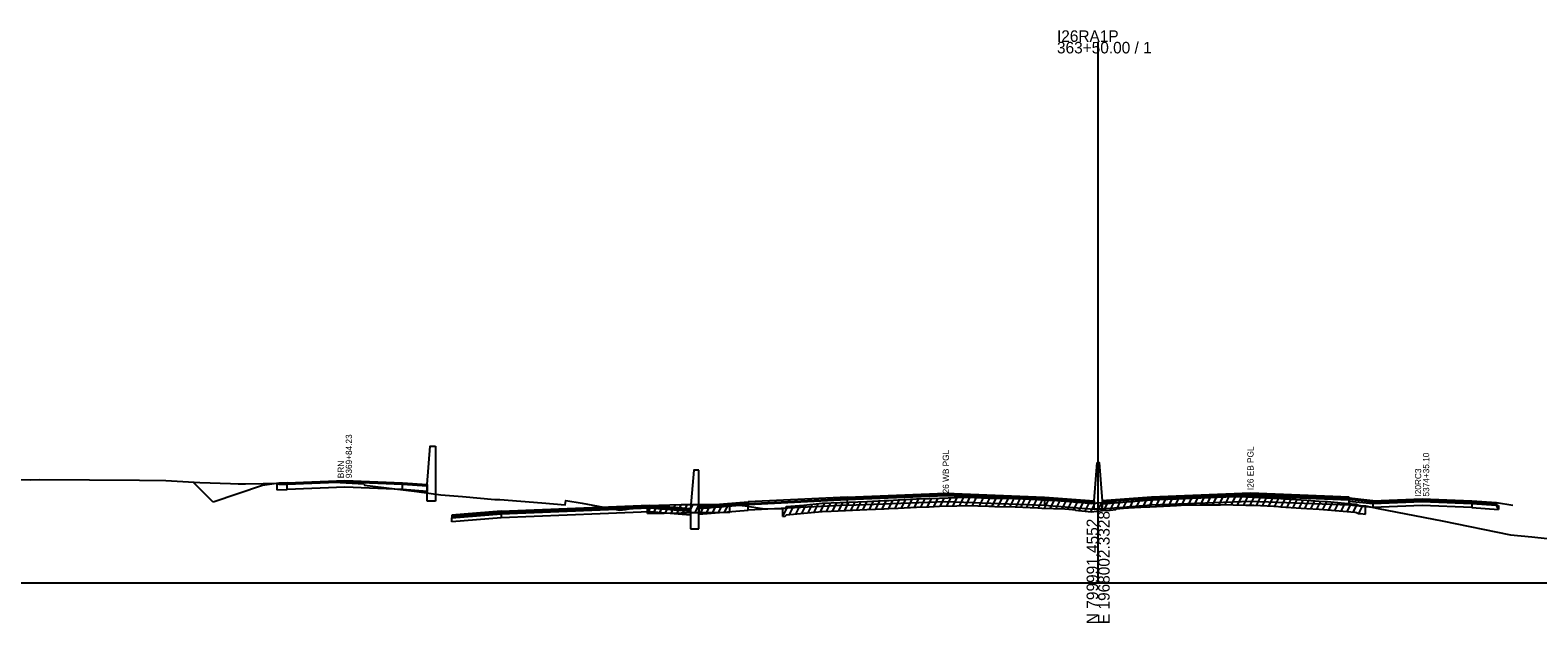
# Model space of a CAD drawing. Extents: x 1017 to 19997, y -1947 to 50737.
# Drawn here: x 14340.6 to 14706.8, y 13490.3 to 13634.3 of the extents above; entities that cross this region are included whole.
import ezdxf

# ---------------------------------------------------------------- set-up
doc = ezdxf.new("R2010")
doc.units = 0
for name, color, linetype in [('RD_GPK_XS_Cell', 7, 'Continuous'), ('RD_XS_Base', 7, 'Continuous'), ('RD_XS_ExGround', 7, 'Continuous'), ('RD_XS_ExPaveRet', 7, 'Continuous'), ('RD_XS_Greenside', 7, 'Continuous'), ('RD_XS_MedBWall', 7, 'Continuous'), ('RD_XS_Pave', 7, 'Continuous'), ('RD_XS_PaveOvlay', 7, 'Continuous'), ('RD_XS_TieSlope', 7, 'Continuous'), ('RD_XS_TX_Notes', 7, 'Continuous')]:
    doc.layers.add(name, color=color, linetype=linetype)

msp = doc.modelspace()

# ---------------------------------------------------------------- linework, layer by layer
at = {"layer": 'RD_GPK_XS_Cell'}
for p, q in [((14600, 13500), (14600, 13631.42)), ((14000, 13500), (14600, 13500)), ((14600, 13500), (15200, 13500))]:
    msp.add_line(p, q, dxfattribs=at)
at = {"layer": 'RD_XS_Base'}
for points in [[(14403, 13524.03), (14400.5, 13523.93)], [(14400.5, 13523.93), (14400.5, 13522.6)], [(14400.5, 13522.6), (14403, 13522.7)], [(14403, 13524.03), (14417, 13524.59), (14431, 13524.03)], [(14403, 13522.7), (14403, 13524.03)], [(14431, 13522.72), (14417, 13523.26), (14403, 13522.7)], [(14431, 13522.72), (14431, 13524.03)], [(14431, 13524.03), (14437, 13523.55)], [(14437, 13522.24), (14431, 13522.72)], [(14437, 13523.55), (14437, 13522.24)], [(14515, 13517.64), (14515, 13518.98)], [(14539.05, 13518.85), (14515, 13517.64)], [(14539.05, 13520.19), (14539.05, 13518.85)], [(14539.05, 13518.85), (14563, 13519.82), (14587, 13518.85)], [(14599, 13519.25), (14587, 13520.19)], [(14587, 13520.19), (14587, 13518.85)], [(14587, 13518.85), (14599, 13517.91)], [(14599, 13517.91), (14599, 13519.25)], [(14601, 13517.91), (14601, 13519.25)], [(14613, 13518.85), (14601, 13517.91)], [(14613, 13518.85), (14613, 13520.19)], [(14660.95, 13518.85), (14637, 13519.82), (14613, 13518.85)], [(14660.95, 13518.85), (14660.95, 13520.19)], [(14660.95, 13518.9), (14660.95, 13519.9)], [(14660.95, 13519.9), (14666.73, 13519.29)], [(14666.73, 13518.29), (14660.95, 13518.9)], [(14661, 13518.85), (14660.95, 13518.85)], [(14661, 13520.19), (14661, 13518.85)], [(14666.73, 13519.29), (14666.73, 13518.29)], [(14690.76, 13518.33), (14678.74, 13518.79), (14666.73, 13518.29)], [(14690.76, 13519.33), (14690.76, 13518.33)], [(14697.26, 13517.83), (14696.76, 13518.87), (14690.76, 13519.33)], [(14690.76, 13519.33), (14696.76, 13518.87), (14697.26, 13518.83)], [(14697.26, 13518.83), (14697.26, 13517.83)], [(14443, 13515.83), (14455, 13516.81)], [(14443, 13514.83), (14443, 13515.83)], [(14455, 13515.81), (14443, 13514.83)], [(14491, 13517.25), (14479, 13516.77), (14455, 13515.81)], [(14455, 13516.81), (14455, 13515.81)], [(14491, 13518.25), (14501, 13517.45)], [(14491, 13517.25), (14491, 13518.25)], [(14501, 13516.45), (14491, 13517.25)], [(14501, 13517.45), (14501, 13516.45)], [(14503, 13518.02), (14503, 13516.68)], [(14503, 13516.68), (14515, 13517.64)], [(14690.76, 13518.33), (14697.26, 13517.83)]]:
    msp.add_lwpolyline(points, dxfattribs=at)
at = {"layer": 'RD_XS_ExGround'}
msp.add_lwpolyline([(14337.99, 13525.12), (14340.57, 13525.08), (14342.85, 13525.12), (14367.13, 13524.96), (14373.55, 13524.89), (14381.74, 13524.38), (14389.24, 13524.14), (14391.1, 13524.11), (14392.91, 13524.06), (14397.2, 13524.15), (14403.93, 13524.24), (14411.6, 13524.52), (14414.45, 13524.46), (14421.67, 13524.11), (14421.77, 13523.71), (14433.82, 13522.31), (14434.49, 13522.22), (14440.35, 13521.42), (14445.62, 13521), (14453.46, 13520.28), (14454.65, 13520.29), (14464.82, 13519.45), (14470.56, 13519), (14470.66, 13520), (14474.65, 13519.39), (14478.57, 13518.68), (14482.11, 13517.96), (14483.73, 13517.7), (14485.22, 13517.87), (14490.53, 13518.84), (14498.71, 13519.04), (14500.63, 13519.09), (14504.46, 13519.09), (14510.53, 13519.16), (14514.23, 13518.71), (14518.92, 13518.03), (14523.38, 13518.1), (14523.94, 13518.2), (14524.31, 13518.53), (14528.48, 13518.92), (14532.99, 13519.36), (14535.14, 13519.42), (14543.78, 13519.8), (14548.03, 13519.99), (14549.15, 13520.06), (14551.43, 13520.18), (14555.89, 13520.4), (14558.99, 13520.52), (14561.5, 13520.61), (14565.65, 13520.74), (14568.12, 13520.83), (14573.43, 13520.63), (14574.11, 13520.61), (14574.93, 13520.59), (14579.84, 13520.52), (14585.39, 13520.25), (14586.34, 13520.2), (14591.88, 13519.97), (14593.79, 13519.84), (14594.34, 13519.8), (14594.54, 13519.65), (14595.25, 13519.6), (14598.37, 13519.29), (14599.6, 13519.43), (14600, 13519.47), (14601.09, 13519.57), (14602.89, 13519.69), (14604.26, 13519.8), (14604.47, 13519.97), (14606.16, 13520.14), (14607.35, 13520.25), (14610.35, 13520.38), (14612.54, 13520.49), (14617.5, 13520.75), (14619.03, 13520.83), (14620.16, 13520.85), (14624.68, 13520.97), (14629.75, 13521.01), (14630.84, 13521.02), (14632.83, 13520.98), (14635.9, 13520.92), (14636.81, 13520.88), (14637.84, 13520.86), (14642.69, 13520.63), (14643.13, 13520.61), (14644.41, 13520.51), (14649.36, 13520.16), (14650.68, 13520.07), (14653.71, 13519.9), (14655.74, 13519.76), (14662.34, 13519.17), (14662.78, 13519.13), (14663.21, 13518.88), (14663.71, 13518.83), (14664.92, 13518.7), (14668.04, 13518.12), (14683.57, 13515.08), (14700.21, 13511.66), (14705.36, 13511.17), (14709.1, 13510.8)], dxfattribs=at)
at = {"layer": 'RD_XS_ExPaveRet'}
for p, q in [((14490.53, 13516.84), (14491.55, 13518.87)), ((14490.53, 13516.84), (14490.53, 13518.84)), ((14491.98, 13516.88), (14492.99, 13518.9)), ((14493.42, 13516.91), (14494.43, 13518.94)), ((14494.86, 13516.95), (14495.88, 13518.97)), ((14496.31, 13516.98), (14497.32, 13519.01)), ((14497.75, 13517.02), (14498.76, 13519.05)), ((14499.2, 13517.06), (14500.21, 13519.08)), ((14500.66, 13517.09), (14501.66, 13519.09)), ((14502.08, 13517.09), (14503.08, 13519.09)), ((14503.51, 13517.09), (14504.51, 13519.09)), ((14504.94, 13517.09), (14505.94, 13519.11)), ((14506.37, 13517.11), (14507.37, 13519.12)), ((14507.81, 13517.13), (14508.82, 13519.14)), ((14509.26, 13517.15), (14510.27, 13519.16)), ((14510.53, 13517.16), (14510.53, 13519.16)), ((14523.38, 13516.1), (14524.61, 13518.56)), ((14525.06, 13516.6), (14526.11, 13518.7)), ((14526.56, 13516.74), (14527.61, 13518.84)), ((14528.05, 13516.88), (14529.1, 13518.98)), ((14529.55, 13517.03), (14530.6, 13519.13)), ((14531.04, 13517.17), (14532.09, 13519.27)), ((14532.55, 13517.32), (14533.58, 13519.38)), ((14534.03, 13517.39), (14535.04, 13519.42)), ((14535.49, 13517.44), (14536.51, 13519.48)), ((14536.97, 13517.5), (14537.99, 13519.55)), ((14538.44, 13517.57), (14539.46, 13519.61)), ((14539.91, 13517.63), (14540.94, 13519.68)), ((14541.39, 13517.7), (14542.41, 13519.74)), ((14542.87, 13517.76), (14543.89, 13519.81)), ((14544.42, 13517.83), (14545.44, 13519.88)), ((14545.98, 13517.9), (14547, 13519.94)), ((14547.54, 13517.97), (14548.57, 13520.02)), ((14549.12, 13518.06), (14550.15, 13520.11)), ((14550.69, 13518.14), (14551.71, 13520.19)), ((14552.26, 13518.22), (14553.28, 13520.27)), ((14553.82, 13518.29), (14554.85, 13520.35)), ((14555.39, 13518.37), (14556.41, 13520.42)), ((14556.96, 13518.44), (14557.98, 13520.48)), ((14558.53, 13518.51), (14559.55, 13520.54)), ((14560.09, 13518.56), (14561.11, 13520.59)), ((14561.65, 13518.61), (14562.67, 13520.64)), ((14563.21, 13518.66), (14564.23, 13520.69)), ((14564.77, 13518.71), (14565.79, 13520.74)), ((14566.33, 13518.76), (14567.35, 13520.8)), ((14567.89, 13518.82), (14568.88, 13520.8)), ((14569.47, 13518.78), (14570.45, 13520.74)), ((14571.21, 13518.71), (14572.19, 13520.67)), ((14572.72, 13518.65), (14573.7, 13520.62)), ((14574.24, 13518.6), (14575.23, 13520.59)), ((14575.72, 13518.58), (14576.71, 13520.57)), ((14577.19, 13518.56), (14578.19, 13520.54)), ((14578.63, 13518.54), (14579.63, 13520.52)), ((14580.06, 13518.51), (14581.04, 13520.46)), ((14581.29, 13518.45), (14582.27, 13520.4)), ((14582.67, 13518.38), (14583.65, 13520.33)), ((14584.1, 13518.31), (14585.07, 13520.26)), ((14585.52, 13518.24), (14586.5, 13520.2)), ((14586.95, 13518.18), (14587.93, 13520.14)), ((14588.38, 13518.12), (14589.36, 13520.08)), ((14589.81, 13518.06), (14590.79, 13520.02)), ((14591.24, 13518), (14592.21, 13519.95)), ((14592.65, 13517.92), (14593.62, 13519.85)), ((14594.06, 13517.82), (14594.96, 13519.62)), ((14595.43, 13517.58), (14596.38, 13519.49)), ((14596.84, 13517.44), (14597.79, 13519.34)), ((14598.25, 13517.3), (14599.3, 13519.4)), ((14599.81, 13517.45), (14600.86, 13519.55)), ((14601.37, 13517.59), (14602.4, 13519.65)), ((14602.9, 13517.69), (14603.94, 13519.77)), ((14604.53, 13517.98), (14605.58, 13520.08)), ((14606.09, 13518.14), (14607.14, 13520.23)), ((14607.69, 13518.26), (14608.71, 13520.31)), ((14609.26, 13518.33), (14610.29, 13520.37)), ((14610.84, 13518.4), (14611.87, 13520.46)), ((14612.42, 13518.49), (14613.45, 13520.54)), ((14614, 13518.57), (14615.03, 13520.62)), ((14615.58, 13518.65), (14616.61, 13520.7)), ((14617.16, 13518.73), (14618.18, 13520.78)), ((14618.74, 13518.81), (14619.75, 13520.84)), ((14620.31, 13518.86), (14621.32, 13520.88)), ((14621.89, 13518.9), (14622.9, 13520.92)), ((14623.39, 13518.94), (14624.4, 13520.96)), ((14624.89, 13518.97), (14625.9, 13520.98)), ((14626.38, 13518.99), (14627.39, 13520.99)), ((14627.87, 13519), (14628.87, 13521)), ((14629.36, 13519.01), (14630.37, 13521.02)), ((14630.85, 13519.02), (14631.84, 13521)), ((14632.37, 13518.99), (14633.36, 13520.97)), ((14633.89, 13518.96), (14634.89, 13520.94)), ((14635.42, 13518.93), (14636.4, 13520.9)), ((14636.93, 13518.88), (14637.92, 13520.85)), ((14638.45, 13518.83), (14639.42, 13520.78)), ((14639.95, 13518.76), (14640.93, 13520.71)), ((14641.45, 13518.68), (14642.43, 13520.64)), ((14642.96, 13518.61), (14643.92, 13520.55)), ((14644.45, 13518.51), (14645.42, 13520.44)), ((14645.95, 13518.4), (14646.92, 13520.33)), ((14647.39, 13518.3), (14648.35, 13520.23)), ((14648.82, 13518.2), (14649.79, 13520.13)), ((14650.25, 13518.1), (14651.22, 13520.04)), ((14651.7, 13518.01), (14652.67, 13519.96)), ((14653.14, 13517.93), (14654.11, 13519.88)), ((14654.58, 13517.84), (14655.55, 13519.78)), ((14656.06, 13517.73), (14657.02, 13519.65)), ((14657.53, 13517.6), (14658.49, 13519.52)), ((14659.01, 13517.47), (14659.97, 13519.39)), ((14660.48, 13517.34), (14661.44, 13519.25)), ((14661.95, 13517.21), (14662.89, 13519.07)), ((14663.33, 13516.87), (14664.28, 13518.77)), ((14664.92, 13516.7), (14664.92, 13518.7)), ((14523.38, 13516.1), (14523.38, 13518.1)), ((14664.79, 13516.72), (14664.92, 13516.99))]:
    msp.add_line(p, q, dxfattribs=at)
for points in [[(14523.38, 13516.1), (14523.94, 13516.2), (14524.31, 13516.53), (14528.48, 13516.92), (14532.99, 13517.36), (14535.14, 13517.42), (14543.78, 13517.8), (14548.03, 13517.99), (14549.15, 13518.06), (14551.43, 13518.18), (14555.89, 13518.4), (14558.99, 13518.52), (14561.5, 13518.61), (14565.65, 13518.74), (14568.12, 13518.83), (14573.43, 13518.63), (14574.11, 13518.61), (14574.93, 13518.59), (14579.84, 13518.52), (14585.39, 13518.25), (14586.34, 13518.2), (14591.88, 13517.97), (14593.79, 13517.84), (14594.34, 13517.8), (14594.54, 13517.65), (14595.25, 13517.6), (14598.37, 13517.29), (14599.6, 13517.43), (14600, 13517.47), (14601.09, 13517.57), (14602.89, 13517.69), (14604.26, 13517.8), (14604.47, 13517.97), (14606.16, 13518.14), (14607.35, 13518.25), (14610.35, 13518.38), (14612.54, 13518.49), (14617.5, 13518.75), (14619.03, 13518.83), (14620.16, 13518.85), (14624.68, 13518.97), (14629.75, 13519.01), (14630.84, 13519.02), (14632.83, 13518.98), (14635.9, 13518.92), (14636.81, 13518.88), (14637.84, 13518.86), (14642.69, 13518.63), (14643.13, 13518.61), (14644.41, 13518.51), (14649.36, 13518.16), (14650.68, 13518.07), (14653.71, 13517.9), (14655.74, 13517.76), (14662.34, 13517.17), (14662.78, 13517.13), (14663.21, 13516.88), (14663.71, 13516.83), (14664.92, 13516.7)], [(14490.53, 13516.84), (14498.71, 13517.04), (14500.63, 13517.09), (14504.46, 13517.09), (14510.53, 13517.16)]]:
    msp.add_lwpolyline(points, dxfattribs=at)
at = {"layer": 'RD_XS_Greenside'}
for points in [[(14397, 13523.63), (14385, 13519.63)], [(14401, 13524.27), (14397, 13523.63)], [(14696.76, 13519.5), (14700.77, 13518.87)]]:
    msp.add_lwpolyline(points, dxfattribs=at)
at = {"layer": 'RD_XS_MedBWall'}
for points in [[(14437, 13523.87), (14437.75, 13533.21), (14439, 13533.21)], [(14439, 13533.21), (14439, 13519.87)], [(14503, 13527.43), (14501.75, 13527.43), (14501, 13518.09)], [(14503, 13513.13), (14503, 13527.43)], [(14599, 13519.91), (14599.75, 13529.25)], [(14599.75, 13529.25), (14600.25, 13529.25), (14601, 13519.91)], [(14437, 13519.87), (14437, 13523.87)], [(14439, 13519.87), (14437, 13519.87)], [(14599, 13517.91), (14599, 13519.25), (14599, 13519.91)], [(14601, 13519.91), (14601, 13519.25), (14601, 13517.91)], [(14501, 13518.09), (14501, 13513.13)], [(14601, 13517.91), (14599, 13517.91)], [(14501, 13513.13), (14503, 13513.13)]]:
    msp.add_lwpolyline(points, dxfattribs=at)
at = {"layer": 'RD_XS_Pave'}
for points in [[(14491, 13518.57), (14479, 13518.09), (14455, 13517.13)], [(14491, 13518.25), (14491, 13518.57)], [(14491, 13518.57), (14501, 13517.77)], [(14503, 13518.36), (14515, 13519.32)], [(14515, 13518.98), (14503, 13518.02)], [(14515, 13519.32), (14539.05, 13520.53)], [(14539.05, 13520.19), (14515, 13518.98)], [(14515, 13518.98), (14515, 13519.32)], [(14587, 13520.19), (14563, 13521.16), (14539.05, 13520.19)], [(14539.05, 13520.53), (14539.05, 13520.19)], [(14587, 13520.53), (14587, 13520.19)], [(14587, 13520.53), (14599, 13519.59)], [(14599, 13519.59), (14599, 13519.25)], [(14613, 13520.53), (14601, 13519.59)], [(14601, 13519.25), (14613, 13520.19)], [(14601, 13519.59), (14601, 13519.25)], [(14660.95, 13520.53), (14637, 13521.49), (14613, 13520.53)], [(14613, 13520.19), (14637, 13521.16), (14660.95, 13520.19)], [(14613, 13520.19), (14613, 13520.53)], [(14660.95, 13520.53), (14661, 13520.53)], [(14660.95, 13520.19), (14660.95, 13520.53)], [(14666.73, 13519.61), (14660.95, 13520.23)], [(14660.95, 13520.23), (14660.95, 13519.9)], [(14661, 13520.19), (14660.95, 13520.19)], [(14661, 13520.53), (14661, 13520.19)], [(14690.76, 13519.65), (14678.74, 13520.11), (14666.73, 13519.61)], [(14666.73, 13519.29), (14678.74, 13519.79), (14690.76, 13519.33)], [(14666.73, 13519.61), (14666.73, 13519.29)], [(14690.76, 13519.33), (14690.76, 13519.65)], [(14690.76, 13519.65), (14696.76, 13519.19)], [(14696.76, 13518.87), (14690.76, 13519.33)], [(14696.76, 13519.19), (14696.76, 13518.87)], [(14455, 13517.13), (14443, 13516.17)], [(14443, 13516.17), (14443, 13515.83)], [(14455, 13516.81), (14479, 13517.77), (14491, 13518.25)], [(14455, 13517.13), (14455, 13516.81)], [(14501, 13517.77), (14501, 13517.45)], [(14503, 13518.02), (14503, 13518.36)]]:
    msp.add_lwpolyline(points, dxfattribs=at)
at = {"layer": 'RD_XS_PaveOvlay'}
for points in [[(14403, 13524.35), (14401, 13524.27)], [(14401, 13524.27), (14401, 13523.95)], [(14401, 13523.95), (14403, 13524.03)], [(14403, 13524.35), (14417, 13524.91), (14431, 13524.35)], [(14403, 13524.03), (14403, 13524.35)], [(14431, 13524.35), (14431, 13524.03)], [(14431, 13524.35), (14437, 13523.87)], [(14437, 13523.87), (14437, 13523.55)], [(14455, 13517.45), (14479, 13518.41), (14491, 13518.89)], [(14491, 13518.89), (14491, 13518.57)], [(14491, 13518.89), (14501, 13518.09)], [(14503, 13518.7), (14515, 13519.66)], [(14503, 13518.36), (14503, 13518.7)], [(14539.05, 13520.87), (14515, 13519.66)], [(14515, 13519.66), (14515, 13519.32)], [(14539.05, 13520.87), (14563, 13521.83), (14587, 13520.87)], [(14587, 13520.53), (14563, 13521.49), (14539.05, 13520.53)], [(14539.05, 13520.53), (14539.05, 13520.87)], [(14587, 13520.87), (14587, 13520.53)], [(14587, 13520.87), (14599, 13519.91)], [(14599, 13519.91), (14599, 13519.59)], [(14613, 13520.87), (14601, 13519.91)], [(14601, 13519.91), (14601, 13519.59)], [(14660.95, 13520.87), (14637, 13521.83), (14613, 13520.87)], [(14613, 13520.53), (14613, 13520.87)], [(14660.95, 13520.87), (14661, 13520.86)], [(14660.95, 13520.53), (14660.95, 13520.87)], [(14666.73, 13519.93), (14660.95, 13520.55)], [(14660.95, 13520.55), (14660.95, 13520.23)], [(14661, 13520.86), (14661, 13520.53)], [(14666.73, 13519.93), (14678.74, 13520.43), (14690.76, 13519.97)], [(14666.73, 13519.61), (14666.73, 13519.93)], [(14690.76, 13519.97), (14690.76, 13519.65)], [(14690.76, 13519.97), (14696.76, 13519.5)], [(14696.76, 13519.5), (14696.76, 13519.19)], [(14455, 13517.45), (14443, 13516.49)], [(14443, 13516.49), (14443, 13516.17)], [(14455, 13517.13), (14455, 13517.45)], [(14501, 13518.09), (14501, 13517.77)]]:
    msp.add_lwpolyline(points, dxfattribs=at)
at = {"layer": 'RD_XS_TieSlope'}
msp.add_lwpolyline([(14385, 13519.63), (14380.34, 13524.29)], dxfattribs=at)

# ---------------------------------------------------------------- texts
at = {"layer": 'RD_GPK_XS_Cell'}
for s, p in [('I26RA1P', (14590, 13631.42)), ('363+50.00 / 1', (14590, 13628.62))]:
    msp.add_text(s, height=2.8, dxfattribs=at).set_placement(p)
for s, p in [('N 799991.4552', (14600, 13490)), ('E 1968002.3328', (14602.8, 13490))]:
    msp.add_text(s, height=2.8, rotation=90, dxfattribs=at).set_placement(p)
at = {"layer": 'RD_XS_TX_Notes'}
for s, p in [(' 9369+84.23', (14418.73, 13524.88)), ('I26 EB PGL', (14637.75, 13522.56)), (' BRN', (14416.77, 13524.88)), ('I26 WB PGL', (14563.75, 13521.19)), (' 5374+35.10', (14680.42, 13520.43)), (' I20RC3', (14678.47, 13520.43))]:
    msp.add_text(s, height=1.5, rotation=90, dxfattribs=at).set_placement(p)

doc.saveas('drawing.dxf')
